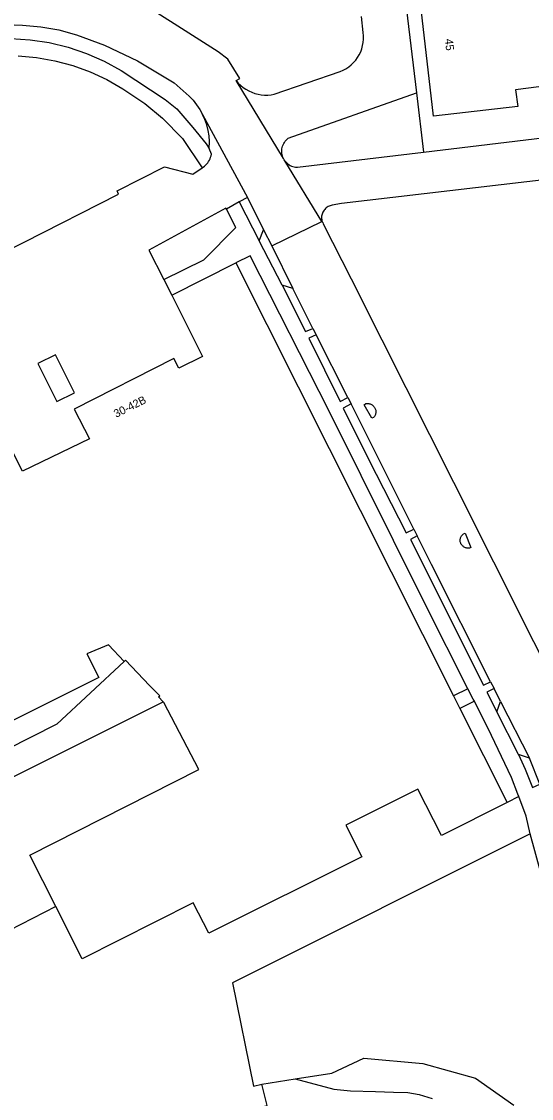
# Model space of a CAD drawing. Extents: x 158132 to 159658, y 385257 to 387209.
# Drawn here: x 159032.3 to 159095.9, y 386462.6 to 386597.1 of the extents above; entities that cross this region are included whole.
import ezdxf

# ---------------------------------------------------------------- set-up
doc = ezdxf.new("R2010")
doc.units = 0
for name, color, linetype in [('IMGEO_Groenvoorziening', 7, 'Continuous'), ('IMGEO_Meer_plas_ven_vijver', 7, 'Continuous'), ('IMGEO_Pand', 7, 'Continuous'), ('IMGEO_Pand_nummerreeks', 7, 'Continuous'), ('IMGEO_Parkeervlak_gesloten', 7, 'Continuous'), ('IMGEO_Parkeervlak_open', 7, 'Continuous'), ('IMGEO_Rijbaan_lokaal_gesloten', 7, 'Continuous'), ('IMGEO_Rijbaan_lokaal_open', 7, 'Continuous'), ('IMGEO_Voetpad_open', 7, 'Continuous')]:
    doc.layers.add(name, color=color, linetype=linetype)

msp = doc.modelspace()

# ---------------------------------------------------------------- linework, layer by layer
at = {"layer": 'IMGEO_Groenvoorziening'}
msp.add_lwpolyline([(159066.42, 386465.03), (159070.99, 386465.77), (159074.99, 386467.61), (159082.36, 386466.96), (159088.96, 386465.12), (159093.72, 386461.76)], dxfattribs=at)
at = {"layer": 'IMGEO_Meer_plas_ven_vijver'}
for points in [[(159062.28, 386464.36), (159066.42, 386465.03)], [(159066.42, 386465.03), (159071.24, 386463.74), (159073.35, 386463.56), (159076.44, 386463.47), (159078.69, 386463.38), (159080.48, 386463.34), (159081.92, 386463.07), (159083.53, 386462.57)]]:
    msp.add_lwpolyline(points, dxfattribs=at)
at = {"layer": 'IMGEO_Pand'}
for points in [[(159106.64, 386609.58), (159106.38, 386611.59), (159122.93, 386613.74), (159122.39, 386617.92), (159136.34, 386619.6), (159139.27, 386595.21), (159125.84, 386593.54), (159125.29, 386598.06), (159108.52, 386595.89), (159109.06, 386591.67), (159102.55, 386590.83), (159102.69, 386589.71), (159093.96, 386588.58), (159094.23, 386586.5), (159083.72, 386585.27), (159081.77, 386601.93), (159093.96, 386603.38), (159093.42, 386607.87), (159106.64, 386609.58)], [(159051.01, 386562.95), (159059.03, 386566.97)], [(159059.03, 386566.97), (159086.21, 386512.87)], [(159051.01, 386562.95), (159054.86, 386555.28), (159051.91, 386553.8), (159051.29, 386555.03), (159038.83, 386548.71), (159040.73, 386544.97), (159032.36, 386540.93), (159028.89, 386547.79), (159026.2, 386546.5), (159024.99, 386548.9), (159009.85, 386541.29)], [(159045.09, 386517.18), (159043.13, 386519.24), (159040.41, 386518.13), (159041.89, 386515.18), (159026.71, 386507.58), (159023.76, 386513.46)], [(159049.94, 386512.15), (159049.37, 386512.76), (159049.51, 386512.88), (159048.25, 386514.19), (159045.25, 386517.33), (159045.09, 386517.18)], [(159086.21, 386512.87), (159086.99, 386511.3)], [(159036.52, 386486.58), (159033.29, 386492.97), (159054.38, 386503.67), (159050.02, 386512.07), (159049.94, 386512.15)], [(159086.99, 386511.3), (159092.88, 386499.58)], [(159092.88, 386499.58), (159084.68, 386495.44), (159081.74, 386501.24), (159072.77, 386496.72), (159074.74, 386492.79), (159055.65, 386483.24), (159053.69, 386487.05), (159039.81, 386480.05), (159036.52, 386486.58)]]:
    msp.add_lwpolyline(points, dxfattribs=at)
at = {"layer": 'IMGEO_Parkeervlak_gesloten'}
msp.add_lwpolyline([(159034.3, 386554.39), (159036.68, 386549.66), (159038.88, 386550.74), (159036.5, 386555.47), (159034.3, 386554.39)], dxfattribs=at)
at = {"layer": 'IMGEO_Parkeervlak_open'}
for points in [[(159055.67, 386581.25), (159055.74, 386582.11), (159055.68, 386582.82), (159055.57, 386583.51), (159055.39, 386584.2), (159055.15, 386584.87), (159054.86, 386585.51)], [(159025.65, 386566.07), (159032.6, 386569.55), (159044.38, 386575.53), (159044.19, 386575.96), (159050.09, 386578.94), (159053.63, 386578.06), (159054.82, 386578.85)], [(159060.48, 386575.13), (159059.42, 386574.58)], [(159057.85, 386573.66), (159057.77, 386573.8), (159048.17, 386568.54), (159050.03, 386564.89)], [(159061.91, 386569.71), (159062.46, 386571.11)], [(159066.12, 386563.76), (159064.8, 386564.17)], [(159091.61, 386510.9), (159092.08, 386512.17)], [(159095.67, 386505.1), (159094.3, 386505.54)]]:
    msp.add_lwpolyline(points, dxfattribs=at)
at = {"layer": 'IMGEO_Rijbaan_lokaal_gesloten'}
for points in [[(159059.05, 386589.73), (159059.51, 386590.01), (159058.02, 386592.39), (159056.81, 386593.34), (159044.57, 386601.15)], [(159024.78, 386596.31), (159024.92, 386596.33), (159030.29, 386596.74), (159032.37, 386596.65), (159034.65, 386596.46), (159036.92, 386596.06), (159039.13, 386595.45), (159042.61, 386594.15), (159046.74, 386592.18), (159051.31, 386589.44), (159053.19, 386587.78), (159053.68, 386587.27), (159054.12, 386586.72), (159054.52, 386586.13), (159054.86, 386585.51)], [(159064.97, 386580.01), (159059.05, 386589.73)], [(159054.86, 386585.51), (159060.48, 386575.13)], [(159065.15, 386579.71), (159065.05, 386579.85), (159064.97, 386580.01)], [(159069.76, 386572.15), (159065.15, 386579.71)], [(159060.48, 386575.13), (159062.46, 386571.11)], [(159063.5, 386569.1), (159069.76, 386572.15)], [(159062.46, 386571.11), (159063.5, 386569.1)]]:
    msp.add_lwpolyline(points, dxfattribs=at)
at = {"layer": 'IMGEO_Rijbaan_lokaal_open'}
for points in [[(159082.47, 386580.81), (159144.99, 386588.33)], [(159145.55, 386582.95), (159072.19, 386574.38), (159071.06, 386574.16), (159070.92, 386574.14), (159070.79, 386574.1), (159070.66, 386574.05), (159070.54, 386573.99), (159070.42, 386573.92), (159070.31, 386573.84), (159070.21, 386573.75), (159070.11, 386573.65), (159070.03, 386573.55), (159069.95, 386573.43), (159069.89, 386573.31), (159069.83, 386573.19), (159069.79, 386573.06), (159069.75, 386572.93), (159069.73, 386572.79), (159069.72, 386572.65), (159069.73, 386572.52), (159069.74, 386572.38), (159069.77, 386572.25), (159069.8, 386572.11), (159069.86, 386571.99)], [(159065.15, 386579.71), (159065.26, 386579.57), (159065.39, 386579.44), (159065.52, 386579.33), (159065.66, 386579.23), (159065.82, 386579.14), (159065.97, 386579.06), (159066.14, 386579), (159066.31, 386578.95), (159066.48, 386578.92), (159066.71, 386578.91), (159082.47, 386580.81)], [(159069.86, 386571.99), (159069.76, 386572.15)], [(159069.86, 386571.99), (159069.92, 386571.86), (159073.41, 386564.98), (159077.26, 386557.36), (159086.18, 386539.58), (159101.17, 386509.73)], [(159063.5, 386569.1), (159066.12, 386563.76)], [(159068.64, 386558.78), (159066.12, 386563.76)], [(159068.64, 386558.78), (159069.05, 386557.98)], [(159073.01, 386550.16), (159069.05, 386557.98)], [(159073.01, 386550.16), (159073.43, 386549.34)], [(159081.26, 386533.72), (159074.81, 386546.61), (159073.43, 386549.34)], [(159075.03, 386549.25), (159075.27, 386549.38), (159075.36, 386549.4), (159075.45, 386549.4), (159075.54, 386549.4), (159075.63, 386549.39), (159075.71, 386549.37), (159075.8, 386549.34), (159075.88, 386549.31), (159075.96, 386549.27), (159076.04, 386549.22), (159076.11, 386549.16), (159076.18, 386549.1), (159076.24, 386549.04), (159076.3, 386548.96), (159076.35, 386548.89), (159076.39, 386548.81), (159076.43, 386548.73), (159076.46, 386548.64), (159076.48, 386548.55), (159076.49, 386548.46), (159076.49, 386548.37), (159076.49, 386548.28), (159076.48, 386548.19), (159076.46, 386548.1), (159076.44, 386548.02), (159076.4, 386547.93), (159076.36, 386547.85), (159076.32, 386547.77), (159076.26, 386547.7), (159076.2, 386547.63), (159076.01, 386547.55), (159075.03, 386549.25)], [(159081.26, 386533.72), (159081.68, 386532.89)], [(159090.83, 386514.64), (159083.47, 386529.31), (159081.68, 386532.89)], [(159088.1, 386531.33), (159088.02, 386531.33), (159087.93, 386531.34), (159087.85, 386531.35), (159087.76, 386531.36), (159087.68, 386531.39), (159087.61, 386531.42), (159087.53, 386531.46), (159087.46, 386531.51), (159087.39, 386531.56), (159087.33, 386531.61), (159087.27, 386531.68), (159087.22, 386531.74), (159087.17, 386531.81), (159087.13, 386531.89), (159087.1, 386531.97), (159087.07, 386532.05), (159087.05, 386532.13), (159087.04, 386532.21), (159087.04, 386532.3), (159087.04, 386532.38), (159087.05, 386532.47), (159087.06, 386532.55), (159087.09, 386532.63), (159087.12, 386532.71), (159087.15, 386532.78), (159087.2, 386532.86), (159087.25, 386532.92), (159087.3, 386532.99), (159087.36, 386533.05), (159087.43, 386533.1), (159087.64, 386533.19), (159088.38, 386531.41), (159088.18, 386531.35), (159088.1, 386531.33)], [(159090.83, 386514.64), (159091.26, 386513.79)], [(159092.08, 386512.17), (159091.26, 386513.79)], [(159092.08, 386512.17), (159095.67, 386505.1)], [(159096.98, 386501.85), (159095.67, 386505.1)]]:
    msp.add_lwpolyline(points, dxfattribs=at)
at = {"layer": 'IMGEO_Voetpad_open'}
for points in [[(159079.74, 386603.44), (159081.58, 386588.19)], [(159059.05, 386589.73), (159059.32, 386589.42), (159059.62, 386589.14), (159059.93, 386588.88), (159060.27, 386588.65), (159060.63, 386588.45), (159061, 386588.28), (159061.39, 386588.14), (159061.79, 386588.03), (159062.19, 386587.96), (159062.6, 386587.92), (159063.01, 386587.92), (159063.42, 386587.95), (159063.82, 386588.02), (159072.03, 386590.86), (159072.41, 386591.02), (159072.77, 386591.22), (159073.11, 386591.44), (159073.42, 386591.7), (159073.72, 386591.98), (159073.98, 386592.29), (159074.22, 386592.62), (159074.43, 386592.97), (159074.61, 386593.34), (159074.75, 386593.72), (159074.85, 386594.11), (159074.92, 386594.51), (159074.96, 386594.92), (159074.96, 386595.33), (159074.92, 386595.73), (159074.7, 386597.72)], [(159024.78, 386596.31), (159025.03, 386594.63), (159028.48, 386594.92), (159030.9, 386594.98), (159033.32, 386594.83), (159035.71, 386594.47), (159038.07, 386593.9), (159040.36, 386593.13), (159042.58, 386592.16), (159044.71, 386591), (159050.19, 386587.39), (159051.65, 386586.21), (159053.63, 386583.89), (159055.32, 386581.82), (159055.67, 386581.25)], [(159031.85, 386592.83), (159034.14, 386592.62), (159036.42, 386592.22), (159038.65, 386591.62), (159040.82, 386590.83), (159042.91, 386589.86), (159044.91, 386588.71), (159047.64, 386586.89), (159049.86, 386585.02), (159052.35, 386582.48), (159054.82, 386578.85)], [(159064.97, 386580.01), (159064.89, 386580.17), (159064.84, 386580.33), (159064.79, 386580.51), (159064.77, 386580.68), (159064.75, 386580.85), (159064.76, 386581.03), (159064.77, 386581.21), (159064.81, 386581.38), (159064.86, 386581.55), (159064.92, 386581.71), (159065, 386581.87), (159065.09, 386582.02), (159065.19, 386582.16), (159065.31, 386582.3), (159065.44, 386582.42), (159065.57, 386582.53), (159081.58, 386588.19)], [(159081.58, 386588.19), (159082.47, 386580.81)], [(159054.82, 386578.85), (159054.93, 386578.93), (159055.09, 386579.05), (159055.24, 386579.18), (159055.38, 386579.32), (159055.51, 386579.47), (159055.62, 386579.63), (159055.72, 386579.8), (159055.8, 386579.98), (159055.87, 386580.16), (159055.93, 386580.35), (159055.96, 386580.55), (159055.67, 386581.25)], [(159059.42, 386574.58), (159057.85, 386573.66)], [(159059.42, 386574.58), (159061.91, 386569.71)], [(159050.03, 386564.89), (159055.03, 386567.36), (159059, 386571.4), (159057.85, 386573.66)], [(159064.8, 386564.17), (159061.91, 386569.71)], [(159088, 386513.77), (159082.68, 386524.24), (159070.67, 386548.43), (159060.8, 386567.86), (159059.03, 386566.97)], [(159050.03, 386564.89), (159051.01, 386562.95)], [(159064.8, 386564.17), (159067.73, 386558.38), (159068.64, 386558.78)], [(159069.05, 386557.98), (159068.14, 386557.58), (159072.03, 386549.64), (159073.01, 386550.16)], [(159073.43, 386549.34), (159072.43, 386548.81), (159075.6, 386542.45), (159080.3, 386533.25), (159081.26, 386533.72)], [(159081.68, 386532.89), (159080.81, 386532.42), (159089.95, 386514.21), (159090.83, 386514.64)], [(159045.09, 386517.18), (159036.68, 386509.35), (159020.76, 386501.3), (159016.48, 386509.83)], [(159091.26, 386513.79), (159090.38, 386513.33), (159091.61, 386510.9)], [(159088, 386513.77), (159086.21, 386512.87)], [(159088.8, 386512.21), (159088.66, 386512.47), (159088, 386513.77)], [(159036.52, 386486.58), (159030.7, 386483.57), (159023.17, 386498.62), (159030.44, 386502.38), (159049.94, 386512.15)], [(159088.8, 386512.21), (159086.99, 386511.3)], [(159094.35, 386500.3), (159094.24, 386500.59), (159093.46, 386502.7), (159090.95, 386507.93), (159088.8, 386512.21)], [(159094.3, 386505.54), (159091.61, 386510.9)], [(159094.3, 386505.54), (159095.16, 386503.71), (159096.05, 386501.45), (159096.98, 386501.85)], [(159094.35, 386500.3), (159092.88, 386499.58)], [(159095.79, 386495.63), (159095.26, 386497.85), (159094.35, 386500.3)], [(159095.79, 386495.63), (159058.61, 386477.03), (159061.23, 386464.11), (159062.28, 386464.36)], [(159112.67, 386450.53), (159110.57, 386454.48), (159107.78, 386460.06), (159105.15, 386465.72), (159102.7, 386471.45), (159101.94, 386473.64), (159099.08, 386483.66), (159095.79, 386495.63)], [(159022.44, 386445.6), (159040.5, 386450.73), (159040.62, 386456.37), (159062.92, 386461.7), (159062.28, 386464.36)]]:
    msp.add_lwpolyline(points, dxfattribs=at)

# ---------------------------------------------------------------- texts
at = {"layer": 'IMGEO_Pand_nummerreeks'}
for s, rotation, p in [('45', 276.2452, (159085.12, 386594.91)), ('30-42B', 26.4477, (159044.07, 386547.6))]:
    msp.add_text(s, height=1, rotation=rotation, dxfattribs=at).set_placement(p)

doc.saveas('drawing.dxf')
